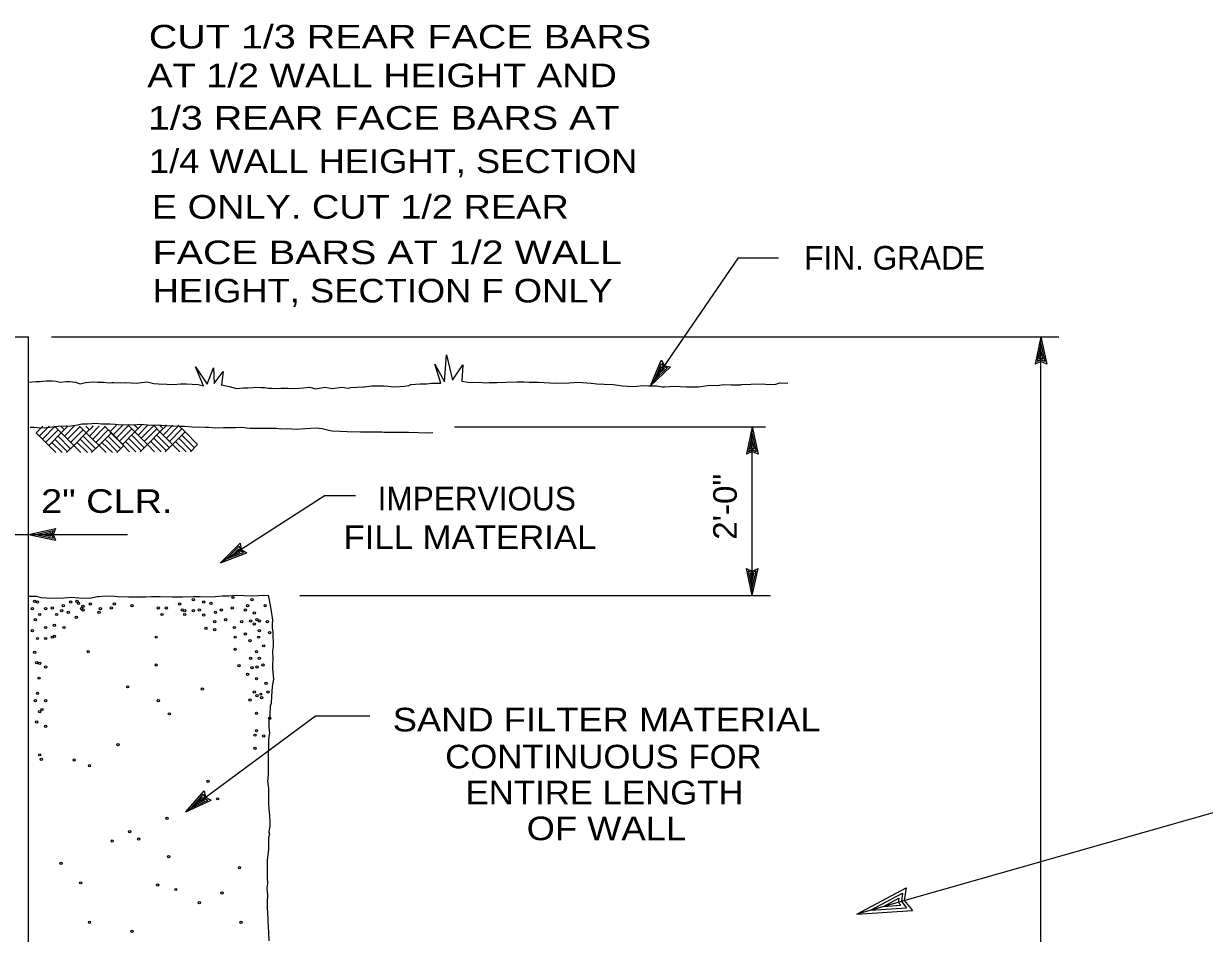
# Model space of a CAD drawing. Extents: x -28.1 to 13.9, y -16.1 to 13.9.
# Drawn here: x -6.82 to -0.57, y -5.87 to -1.05 of the extents above; entities that cross this region are included whole.
import ezdxf
from ezdxf.enums import TextEntityAlignment as Align

# ---------------------------------------------------------------- set-up
doc = ezdxf.new("R2010")
doc.units = 0
doc.header["$LTSCALE"] = 0.05
doc.layers.add('1', color=7, linetype='Continuous', lineweight=13)

msp = doc.modelspace()

# ---------------------------------------------------------------- linework, layer by layer
at = {"layer": '1'}
for p, q in [((-3.03404, -2.29331), (-2.82204, -2.29331)), ((-6.66904, -2.71131), (-1.33704, -2.71131)), ((-1.43204, -2.71131), (-1.46304, -2.85531)), ((-1.43204, -2.74831), (-1.45204, -2.84231)), ((-1.43204, -10.71431), (-1.43204, -2.71131)), ((-1.43204, -2.71131), (-1.40104, -2.85531)), ((-1.43204, -2.74831), (-1.41204, -2.84231)), ((-1.43204, -2.78431), (-1.44104, -2.82931)), ((-1.43204, -2.78431), (-1.42204, -2.82931)), ((-3.49904, -2.97131), (-3.39204, -2.87031)), ((-3.47804, -2.94031), (-3.44104, -2.85231)), ((-3.47804, -2.94031), (-3.40804, -2.87431)), ((-3.45804, -2.91131), (-3.44104, -2.86831)), ((-3.44104, -2.85231), (-3.43004, -2.87031)), ((-3.44104, -2.86831), (-3.43504, -2.87731)), ((-3.43004, -2.87031), (-3.40804, -2.87431)), ((-1.43204, -2.83331), (-1.45204, -2.84231)), ((-1.43204, -2.82531), (-1.44104, -2.82931)), ((-1.42204, -2.82931), (-1.43204, -2.82531)), ((-1.41204, -2.84231), (-1.43204, -2.83331)), ((-3.45804, -2.91131), (-3.42504, -2.87931)), ((-3.43504, -2.87731), (-3.42504, -2.87931)), ((-6.75004, -3.21931), (-6.71504, -3.18431)), ((-6.73404, -3.23631), (-6.68204, -3.18431)), ((-6.71704, -3.25231), (-6.65104, -3.18631)), ((-6.61804, -3.21931), (-6.65304, -3.18431)), ((-6.60104, -3.20331), (-6.62004, -3.18431)), ((-6.61804, -3.21931), (-6.58204, -3.18431)), ((-6.61804, -3.21931), (-6.58204, -3.18431)), ((-6.60104, -3.23631), (-6.54904, -3.18431)), ((-6.58404, -3.18631), (-6.58704, -3.18431)), ((-6.58404, -3.25231), (-6.51804, -3.18631)), ((-6.48504, -3.21931), (-6.52004, -3.18431)), ((-6.46804, -3.20331), (-6.48704, -3.18431)), ((-6.48504, -3.21931), (-6.44904, -3.18431)), ((-6.46804, -3.23631), (-6.41604, -3.18431)), ((-6.45104, -3.18631), (-6.45404, -3.18431)), ((-6.45104, -3.25231), (-6.38504, -3.18631)), ((-6.35204, -3.21931), (-6.38804, -3.18431)), ((-6.36004, -3.21431), (-6.32504, -3.17931)), ((-6.34404, -3.23131), (-6.29204, -3.17931)), ((-6.32704, -3.24731), (-6.26104, -3.18131)), ((-6.22804, -3.21431), (-6.26304, -3.17931)), ((-6.21104, -3.19831), (-6.23004, -3.17931)), ((-6.22804, -3.21431), (-6.19204, -3.17931)), ((-6.22804, -3.21431), (-6.19204, -3.17931)), ((-6.21104, -3.23131), (-6.15904, -3.17931)), ((-6.19404, -3.18131), (-6.19704, -3.17931)), ((-6.19404, -3.24731), (-6.12804, -3.18131)), ((-6.09504, -3.21431), (-6.13004, -3.17931)), ((-6.07804, -3.19831), (-6.09704, -3.17931)), ((-6.09504, -3.21431), (-6.05904, -3.17931)), ((-6.07804, -3.23131), (-6.02604, -3.17931)), ((-6.06104, -3.18131), (-6.06404, -3.17931)), ((-6.06104, -3.24731), (-5.99504, -3.18131)), ((-5.96204, -3.21431), (-5.99804, -3.17931)), ((-6.70104, -3.27031), (-6.63404, -3.20331)), ((-6.68404, -3.28631), (-6.61804, -3.21931)), ((-6.56804, -3.30331), (-6.63404, -3.23631)), ((-6.55104, -3.28631), (-6.61804, -3.21931)), ((-6.56804, -3.27031), (-6.50104, -3.20331)), ((-6.55104, -3.28631), (-6.48504, -3.21931)), ((-6.43504, -3.30331), (-6.50104, -3.23631)), ((-6.43504, -3.27031), (-6.36904, -3.20331)), ((-6.41804, -3.28631), (-6.35204, -3.21931)), ((-6.30204, -3.30331), (-6.36904, -3.23631)), ((-6.28604, -3.28631), (-6.35204, -3.21931)), ((-6.31104, -3.26531), (-6.24404, -3.19831)), ((-6.29404, -3.28131), (-6.22804, -3.21431)), ((-6.19404, -3.31431), (-6.26104, -3.24731)), ((-6.17804, -3.29831), (-6.24404, -3.23131)), ((-6.16104, -3.28131), (-6.22804, -3.21431)), ((-6.17804, -3.26531), (-6.11104, -3.19831)), ((-6.16104, -3.28131), (-6.09504, -3.21431)), ((-6.06104, -3.31431), (-6.12804, -3.24731)), ((-6.04504, -3.29831), (-6.11104, -3.23131)), ((-6.04504, -3.26531), (-5.97904, -3.19831)), ((-6.02804, -3.28131), (-5.96204, -3.21431)), ((-5.92904, -3.31431), (-5.99504, -3.24731)), ((-5.91204, -3.29831), (-5.97904, -3.23131)), ((-5.89604, -3.28131), (-5.96204, -3.21431)), ((-4.53604, -3.18831), (-2.89004, -3.18831)), ((-2.96004, -3.18831), (-2.99104, -3.33231)), ((-2.96004, -3.22531), (-2.98004, -3.31931)), ((-2.96004, -4.08131), (-2.96004, -3.18831)), ((-2.96004, -3.18831), (-2.92904, -3.33231)), ((-2.96004, -3.22531), (-2.94004, -3.31931)), ((-6.61304, -3.32431), (-6.66804, -3.27031)), ((-6.58404, -3.31931), (-6.65104, -3.25231)), ((-6.58904, -3.32431), (-6.55104, -3.28631)), ((-6.51304, -3.32431), (-6.55104, -3.28631)), ((-6.47904, -3.32431), (-6.53404, -3.27031)), ((-6.45104, -3.31931), (-6.51804, -3.25231)), ((-6.45704, -3.32431), (-6.41804, -3.28631)), ((-6.34704, -3.32431), (-6.40204, -3.27031)), ((-6.31904, -3.31931), (-6.38504, -3.25231)), ((-6.32404, -3.32431), (-6.28604, -3.28631)), ((-6.22304, -3.31931), (-6.27804, -3.26531)), ((-6.19904, -3.31931), (-6.16104, -3.28131)), ((-6.12304, -3.31931), (-6.16104, -3.28131)), ((-6.08904, -3.31931), (-6.14404, -3.26531)), ((-6.06704, -3.31931), (-6.02804, -3.28131)), ((-5.95704, -3.31931), (-6.01204, -3.26531)), ((-5.93404, -3.31931), (-5.89604, -3.28131)), ((-2.96004, -3.31031), (-2.98004, -3.31931)), ((-2.96004, -3.26131), (-2.96904, -3.30631)), ((-2.96004, -3.30231), (-2.96904, -3.30631)), ((-2.96004, -3.26131), (-2.95004, -3.30631)), ((-2.95004, -3.30631), (-2.96004, -3.30231)), ((-2.94004, -3.31931), (-2.96004, -3.31031)), ((-5.22004, -3.55131), (-5.06004, -3.55131)), ((-6.79104, -3.75731), (-6.64704, -3.72631)), ((-6.75404, -3.75731), (-6.66004, -3.73731)), ((-6.71804, -3.75731), (-6.67304, -3.74731)), ((-6.67304, -3.74731), (-6.67704, -3.75731)), ((-6.66004, -3.73731), (-6.66904, -3.75731)), ((-6.79104, -3.75731), (-6.64704, -3.78831)), ((-6.75404, -3.75731), (-6.66004, -3.77731)), ((-6.71804, -3.75731), (-6.67304, -3.76631)), ((-6.67704, -3.75731), (-6.67304, -3.76631)), ((-6.66904, -3.75731), (-6.66004, -3.77731)), ((-5.77404, -3.90731), (-5.63604, -3.85531)), ((-5.74304, -3.88731), (-5.67504, -3.81931)), ((-5.74304, -3.88731), (-5.65304, -3.85331)), ((-5.71304, -3.86831), (-5.68004, -3.83531)), ((-5.71304, -3.86831), (-5.67004, -3.85131)), ((-5.68004, -3.83531), (-5.67804, -3.84531)), ((-5.67804, -3.84531), (-5.67004, -3.85131)), ((-5.67504, -3.81931), (-5.67104, -3.84131)), ((-5.67104, -3.84131), (-5.65304, -3.85331)), ((-2.96004, -4.08131), (-2.99104, -3.93731)), ((-2.96004, -4.04431), (-2.98004, -3.95031)), ((-2.98004, -3.95031), (-2.96004, -3.95931)), ((-2.96004, -4.00831), (-2.97004, -3.96331)), ((-2.97004, -3.96331), (-2.96004, -3.96731)), ((-2.96004, -4.08131), (-2.92904, -3.93731)), ((-2.96004, -4.04431), (-2.94004, -3.95031)), ((-2.96004, -3.95931), (-2.94004, -3.95031)), ((-2.96004, -4.00831), (-2.95104, -3.96331)), ((-2.96004, -3.96731), (-2.95104, -3.96331)), ((-5.35404, -4.08131), (-2.86404, -4.08131)), ((-5.95804, -5.22631), (-5.86104, -5.11531)), ((-5.95804, -5.22631), (-5.82404, -5.16531)), ((-5.92804, -5.20431), (-5.86504, -5.13231)), ((-5.92804, -5.20431), (-5.84104, -5.16431)), ((-5.89904, -5.18331), (-5.86904, -5.14831)), ((-5.89904, -5.18331), (-5.85804, -5.16331)), ((-5.86904, -5.14831), (-5.86604, -5.15831)), ((-5.86604, -5.15831), (-5.85804, -5.16331)), ((-5.86504, -5.13231), (-5.86004, -5.15331)), ((-5.86004, -5.15331), (-5.84104, -5.16431))]:
    msp.add_line(p, q, dxfattribs=at)
at = {"layer": '1', "lineweight": 25}
for p, q in [((-7.63204, -2.71131), (-6.79104, -2.71131)), ((-6.79104, -10.78531), (-6.79104, -2.71131)), ((-2.33504, -5.74731), (-2.16504, -5.65731)), ((-2.26604, -5.72731), (-2.18404, -5.68331)), ((-2.18404, -5.68331), (-2.18704, -5.70531)), ((-2.16504, -5.65731), (-2.17104, -5.70031)), ((-2.40604, -5.76731), (-2.11204, -5.74831)), ((-2.33504, -5.74731), (-2.14304, -5.73431)), ((-2.26604, -5.72731), (-2.17404, -5.72031)), ((-2.18704, -5.70531), (-2.17404, -5.72031)), ((-2.17104, -5.70031), (-2.14304, -5.73431))]:
    msp.add_line(p, q, dxfattribs=at)
at = {"layer": '1'}
for points in [[(-3.03404, -2.29331), (-3.49904, -2.97131), (-3.44304, -2.83531)], [(-3.44304, -2.83531), (-3.42504, -2.86431), (-3.39204, -2.87031)], [(-1.40104, -2.85531), (-1.43204, -2.84131), (-1.46304, -2.85531)], [(-6.38004, -3.32431), (-6.48504, -3.21931), (-6.44904, -3.18431)], [(-5.99004, -3.31931), (-6.09504, -3.21431), (-6.05904, -3.17931)], [(-6.64604, -3.32431), (-6.68404, -3.28631), (-6.75004, -3.21931)], [(-6.25604, -3.31931), (-6.29404, -3.28131), (-6.36004, -3.21431)], [(-2.92904, -3.33231), (-2.96004, -3.31831), (-2.99104, -3.33231)], [(-5.22004, -3.55131), (-5.77404, -3.90731), (-5.67004, -3.80331)], [(-6.64704, -3.72631), (-6.66104, -3.75731), (-6.64704, -3.78831)], [(-7.20204, -3.75731), (-6.87804, -3.75731), (-6.79104, -3.75731), (-6.26604, -3.75731)], [(-5.67004, -3.80331), (-5.66504, -3.83731), (-5.63604, -3.85531)], [(-2.99104, -3.93731), (-2.96004, -3.95131), (-2.92904, -3.93731)], [(-5.95804, -5.22631), (-5.27104, -4.71731), (-4.98404, -4.71731)], [(-5.86104, -5.11531), (-5.85404, -5.14931), (-5.82404, -5.16531)]]:
    msp.add_lwpolyline(points, dxfattribs=at)
at = {"layer": '1', "lineweight": 25}
for points in [[(-6.79104, -2.95131), (-6.75104, -2.94831), (-6.72904, -2.94731), (-6.69804, -2.94431), (-6.66304, -2.94431), (-6.64404, -2.94631), (-6.62304, -2.95131), (-6.58904, -2.94731), (-6.57404, -2.94731), (-6.54204, -2.95131), (-6.51704, -2.96031), (-6.48904, -2.95231), (-6.45404, -2.95031), (-6.42604, -2.95131), (-6.39404, -2.95131), (-6.36804, -2.95531), (-6.34904, -2.95331), (-6.33904, -2.95231), (-6.30204, -2.95431), (-6.27504, -2.95331), (-6.22004, -2.95631), (-6.16204, -2.95031), (-6.12704, -2.95831), (-6.10304, -2.95931), (-6.05904, -2.96231), (-6.02404, -2.96431), (-5.98704, -2.95931), (-5.95504, -2.95931), (-5.92504, -2.96231), (-5.89204, -2.96331), (-5.86504, -2.97031), (-5.90704, -2.87031), (-5.84504, -2.96231), (-5.81104, -2.87531), (-5.80804, -2.95831), (-5.76004, -2.89531), (-5.76904, -2.96731), (-5.76904, -2.96531), (-5.72804, -2.97331), (-5.69004, -2.98431), (-5.65404, -2.98131), (-5.62904, -2.98131), (-5.60304, -2.97931), (-5.56804, -2.97831), (-5.56104, -2.98031), (-5.54204, -2.98031), (-5.52004, -2.98231), (-5.50404, -2.98231), (-5.48704, -2.98431), (-5.45504, -2.98231), (-5.41804, -2.98331), (-5.40404, -2.98431), (-5.35404, -2.98331), (-5.33504, -2.98131), (-5.32204, -2.97931), (-5.30304, -2.97831), (-5.27004, -2.98631), (-5.22204, -2.97831), (-5.18404, -2.98431), (-5.13204, -2.97831), (-5.09704, -2.98331), (-5.08504, -2.97931), (-5.02004, -2.97531), (-5.01404, -2.97531), (-4.97304, -2.97031), (-4.90804, -2.97031), (-4.85104, -2.97531), (-4.80004, -2.97231), (-4.77804, -2.96831), (-4.76704, -2.96431), (-4.71704, -2.96031), (-4.68304, -2.95931), (-4.65704, -2.95631), (-4.62004, -2.95731), (-4.60904, -2.95631), (-4.64104, -2.85631), (-4.58904, -2.94931), (-4.57904, -2.80631), (-4.54604, -2.94031), (-4.49204, -2.85931), (-4.49804, -2.94531), (-4.45304, -2.95231), (-4.40604, -2.95131), (-4.37004, -2.95431), (-4.35204, -2.95331), (-4.31104, -2.95231), (-4.26204, -2.95131), (-4.20704, -2.94931), (-4.16804, -2.95031), (-4.14004, -2.95131), (-4.09204, -2.95131), (-4.00204, -2.95631), (-3.93004, -2.95531), (-3.88204, -2.95131), (-3.81304, -2.95631), (-3.78204, -2.95931), (-3.74404, -2.96131), (-3.69604, -2.96431), (-3.64604, -2.97031), (-3.59404, -2.97331), (-3.56904, -2.97231)], [(-3.56904, -2.97231), (-3.53704, -2.96931), (-3.51004, -2.97131), (-3.46604, -2.97131), (-3.43704, -2.97531), (-3.42504, -2.97531), (-3.37504, -2.97231), (-3.30804, -2.97531), (-3.26804, -2.97631), (-3.24404, -2.97531), (-3.18404, -2.96731), (-3.14604, -2.96831), (-3.11104, -2.96431), (-3.07204, -2.96531), (-3.02104, -2.96531), (-3.01704, -2.96431), (-2.96804, -2.96131), (-2.90404, -2.95931), (-2.89004, -2.96131), (-2.84004, -2.96431), (-2.81504, -2.95431), (-2.77104, -2.95731)], [(-6.78204, -3.18931), (-6.76004, -3.18931), (-6.72504, -3.19231), (-6.69604, -3.19131), (-6.63404, -3.18331), (-6.56504, -3.18231), (-6.53204, -3.17631), (-6.50804, -3.17131), (-6.47804, -3.17231), (-6.45604, -3.17031), (-6.43204, -3.16831), (-6.40504, -3.17131), (-6.35904, -3.17231), (-6.33204, -3.17331), (-6.30004, -3.17631), (-6.26004, -3.17531), (-6.23104, -3.17731), (-6.19904, -3.17331), (-6.16104, -3.17731), (-6.14604, -3.17931), (-6.10704, -3.17731), (-6.07104, -3.18031), (-6.03204, -3.18231), (-5.99404, -3.18331), (-5.96504, -3.18331), (-5.92504, -3.18831), (-5.85404, -3.18931), (-5.83604, -3.19031), (-5.80004, -3.19331), (-5.75904, -3.19131), (-5.71704, -3.19131), (-5.69604, -3.19131), (-5.66204, -3.19031), (-5.62004, -3.19431), (-5.57004, -3.19531), (-5.55504, -3.19431), (-5.51304, -3.19431), (-5.49004, -3.19431), (-5.48004, -3.19531), (-5.45304, -3.19831), (-5.42004, -3.19631), (-5.37404, -3.20031), (-5.32704, -3.19731), (-5.26804, -3.19231), (-5.23704, -3.19731), (-5.19404, -3.20731), (-5.18304, -3.20931), (-5.10504, -3.21231), (-5.03404, -3.21331), (-5.01404, -3.21331), (-4.92004, -3.21331), (-4.91004, -3.21531), (-4.83704, -3.21531), (-4.77904, -3.21531), (-4.72804, -3.21831), (-4.67604, -3.21931), (-4.65004, -3.21731)], [(-6.79104, -4.08431), (-6.74904, -4.08431), (-6.72604, -4.09131), (-6.69504, -4.09331), (-6.65304, -4.09531), (-6.60304, -4.09331), (-6.56504, -4.09031), (-6.52504, -4.09231), (-6.46604, -4.09431), (-6.42704, -4.08631), (-6.42204, -4.08531), (-6.38104, -4.08231), (-6.33304, -4.08431), (-6.31804, -4.08531), (-6.26104, -4.08731), (-6.21504, -4.08831), (-6.17204, -4.08731), (-6.13904, -4.08531), (-6.09304, -4.08531), (-6.02804, -4.08731), (-6.01904, -4.08731), (-5.97604, -4.08831), (-5.91804, -4.08631), (-5.88204, -4.08631), (-5.82104, -4.08731), (-5.76604, -4.08331), (-5.73104, -4.08231), (-5.68904, -4.07931), (-5.64904, -4.08131), (-5.60304, -4.08231), (-5.57404, -4.08131), (-5.54704, -4.07931), (-5.52104, -4.08131), (-5.52304, -4.07931), (-5.51404, -4.12231), (-5.50704, -4.16431), (-5.50004, -4.21131), (-5.50104, -4.23231), (-5.50104, -4.25231), (-5.49704, -4.27531), (-5.49604, -4.34931), (-5.49804, -4.36231), (-5.50004, -4.37331), (-5.49704, -4.41931), (-5.49904, -4.44431), (-5.50004, -4.46931), (-5.49404, -4.52331), (-5.50104, -4.56231), (-5.50404, -4.61631), (-5.50604, -4.65031), (-5.51104, -4.66631), (-5.51304, -4.70831), (-5.51604, -4.73531), (-5.51904, -4.74431), (-5.51804, -4.77531), (-5.51604, -4.80931), (-5.51804, -4.82731), (-5.52004, -4.84631), (-5.52104, -4.89031), (-5.52204, -4.92231), (-5.52304, -4.96431), (-5.52304, -4.99231), (-5.52304, -5.01931), (-5.52404, -5.05731), (-5.52604, -5.06031), (-5.52304, -5.09031), (-5.52104, -5.10231), (-5.52104, -5.15231), (-5.52004, -5.18131), (-5.51804, -5.21031), (-5.51604, -5.24331), (-5.51404, -5.28331), (-5.51404, -5.30231), (-5.51804, -5.33131), (-5.51604, -5.34431), (-5.52104, -5.36131), (-5.52104, -5.39831), (-5.52004, -5.42531), (-5.52304, -5.43731), (-5.52804, -5.48431), (-5.52704, -5.52531), (-5.52804, -5.53331), (-5.52704, -5.57831), (-5.52504, -5.60431), (-5.52904, -5.63031), (-5.52604, -5.66731), (-5.52704, -5.70131), (-5.52704, -5.74131), (-5.52604, -5.75431), (-5.52404, -5.79831), (-5.52304, -5.83631), (-5.52004, -5.86431), (-5.51904, -5.90931)], [(1.52496, -4.64931), (-2.40604, -5.76731), (-2.14604, -5.62931)], [(-2.14604, -5.62931), (-2.15604, -5.69631), (-2.11204, -5.74831)]]:
    msp.add_lwpolyline(points, dxfattribs=at)
at = {"layer": '1'}
for centre in [(-6.75804, -4.11131), (-6.74304, -4.11531), (-6.56804, -4.11531), (-6.53404, -4.11131), (-6.52604, -4.12231), (-6.46404, -4.12631), (-6.33604, -4.12631), (-5.99104, -4.12631), (-5.91804, -4.10331), (-5.86304, -4.11531), (-5.82504, -4.12231), (-5.70804, -4.09131), (-5.60804, -4.10331), (-6.77004, -4.15031), (-6.73104, -4.18131), (-6.70004, -4.15031), (-6.66504, -4.14631), (-6.64204, -4.18131), (-6.61504, -4.16131), (-6.60704, -4.13431), (-6.58004, -4.16931), (-6.51004, -4.15031), (-6.50304, -4.13831), (-6.50304, -4.15731), (-6.41704, -4.16931), (-6.41004, -4.15031), (-6.35204, -4.14631), (-6.24304, -4.13431), (-6.10404, -4.14631), (-6.08404, -4.18131), (-6.06104, -4.14631), (-5.97604, -4.15731), (-5.96404, -4.16131), (-5.96404, -4.18131), (-5.91804, -4.16131), (-5.88704, -4.15731), (-5.86304, -4.18431), (-5.80104, -4.16931), (-5.77004, -4.15731), (-5.71204, -4.14631), (-5.64304, -4.15731), (-5.63104, -4.13431), (-5.59604, -4.17331), (-5.53804, -4.13431), (-6.75404, -4.20831), (-6.70004, -4.25031), (-6.65404, -4.23931), (-6.60304, -4.25031), (-6.53704, -4.19631), (-5.85204, -4.25431), (-5.80504, -4.21931), (-5.74704, -4.20831), (-5.70104, -4.25031), (-5.66204, -4.21931), (-5.61504, -4.21531), (-5.59604, -4.23131), (-5.58104, -4.20831), (-5.56904, -4.21531), (-5.52604, -4.21931), (-6.77004, -4.26631), (-6.74304, -4.30831), (-6.70004, -4.30831), (-6.66504, -4.30131), (-6.65404, -4.29731), (-6.11504, -4.30131), (-5.80504, -4.26231), (-5.69704, -4.30131), (-5.64304, -4.28531), (-5.57304, -4.30131), (-5.56904, -4.26631), (-5.51504, -4.27731), (-6.47504, -4.37831), (-5.69704, -4.36631), (-5.61904, -4.32031), (-5.58404, -4.37831), (-5.54604, -4.34731), (-6.75804, -4.38231), (-6.74704, -4.43631), (-6.73104, -4.44031), (-5.61504, -4.41331), (-5.56904, -4.41331), (-6.70004, -4.45931), (-6.11504, -4.44831), (-5.67704, -4.45231), (-5.63104, -4.49831), (-5.60804, -4.46331), (-5.58104, -4.45931), (-5.55004, -4.44831), (-6.73504, -4.51831), (-6.26604, -4.56431), (-5.58404, -4.52131), (-5.53404, -4.54531), (-6.74304, -4.59931), (-5.87104, -4.57631), (-5.59604, -4.59131), (-5.58104, -4.61131), (-5.56104, -4.60331), (-5.55704, -4.62231), (-5.52304, -4.59131), (-6.75404, -4.63831), (-6.72004, -4.68431), (-6.70004, -4.63831), (-6.10404, -4.63831), (-5.61904, -4.63431), (-6.74704, -4.75031), (-6.73104, -4.69631), (-6.04504, -4.70731), (-5.58404, -4.70431), (-5.51504, -4.73131), (-6.70004, -4.77331), (-5.58404, -4.79631), (-6.31704, -4.87031), (-5.59204, -4.82031), (-5.54604, -4.82431), (-6.73104, -4.92431), (-5.59204, -4.88931), (-6.72304, -4.94831), (-6.54904, -4.95131), (-6.46804, -4.98231), (-5.84004, -5.06431), (-5.79004, -5.15731), (-6.05704, -5.26131), (-6.25504, -5.33131), (-6.20804, -5.37031), (-6.34804, -5.38131), (-6.61904, -5.49831), (-6.04904, -5.46331), (-5.67404, -5.52131), (-6.51404, -5.60231), (-6.10704, -5.61431), (-6.01104, -5.63731), (-5.76704, -5.65631), (-5.88704, -5.70731), (-6.46804, -5.81131), (-5.66604, -5.81131), (-6.24304, -5.85831)]:
    msp.add_circle(centre, 0.006, dxfattribs=at)

# ---------------------------------------------------------------- texts
for s, width, p in [('CUT 1/3 REAR FACE BARS', 1.25, (-6.15404, -1.18431)), ('AT 1/2 WALL HEIGHT AND', 1.2, (-6.16204, -1.38931)), ('1/3 REAR FACE BARS AT', 1.25, (-6.15904, -1.61431)), ('1/4 WALL HEIGHT, SECTION', 1.15, (-6.15304, -1.84331)), ('E ONLY. CUT 1/2 REAR', 1.2, (-6.13804, -2.08531)), ('FACE BARS AT 1/2 WALL', 1.25, (-6.13404, -2.32631)), ('HEIGHT, SECTION F ONLY', 1.15, (-6.13404, -2.52931)), ('2" CLR.', 1.2, (-6.72404, -3.64331)), ('SAND FILTER MATERIAL', 1.15, (-4.86304, -4.80031))]:
    msp.add_text(s, height=0.125, dxfattribs=dict(at, width=width)).set_placement(p)
for s, p in [('FIN. GRADE', (-2.68504, -2.35531)), ('IMPERVIOUS', (-4.94304, -3.63031))]:
    msp.add_text(s, height=0.125, dxfattribs=at).set_placement(p)
at = {"layer": '1', "width": 1.05}
msp.add_text('2\'-0"', height=0.125, rotation=90, dxfattribs=at).set_placement((-3.04204, -3.61096), align=Align.CENTER)
at = {"layer": '1'}
for s, width, p in [('FILL MATERIAL', 1.1, (-4.45445, -3.83431)), ('CONTINUOUS FOR', 1.1, (-3.74786, -4.99631)), ('ENTIRE LENGTH', 1.1, (-3.74185, -5.18631)), ('OF WALL', 1.15, (-3.73229, -5.37631))]:
    msp.add_text(s, height=0.125, dxfattribs=dict(at, width=width)).set_placement(p, align=Align.CENTER)

doc.saveas('drawing.dxf')
